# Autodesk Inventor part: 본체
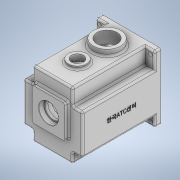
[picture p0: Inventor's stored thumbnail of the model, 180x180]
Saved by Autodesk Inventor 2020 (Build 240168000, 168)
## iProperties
Created: 2022-01
Part Number: 본체
Material: 일반
Document SubType Name: Modeling
Designer: user
Density: 1 g/cm^3
Appearance: 기본값
Author: user
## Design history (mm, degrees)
sketch "스케치1"
  geometry: L1 (-49, -55)-(49, -55); L2 (49, -55)-(49, 55); L3 (49, 55)-(-49, 55); L4 (-49, 55)-(-49, -55); L5 (-49, -55)-(49, 55); L6 (49, -55)-(-49, 55); 1 further point
  constraints: 12 end point, 2 midpoint, 2 parallel, 1 horizontal, 1 perpendicular
  dimensions: "d0" = 98 distance of L2.end L3.end; "d1" = 110 distance of L1.end L2.end
extrude "돌출1" new body sketch "스케치1" distance "d2" = 130; taper "d3" = 0 deg
sketch "스케치2"
  geometry: L1 (82, -130)-(98, -130); L2 (98, -130)-(98, -10); L3 (98, -10)-(82, -10); L4 (82, -10)-(82, -130); L5 (82, -130)-(98, -10); L6 (98, -130)-(82, -10); L7 (0, -130)-(16, -130); L8 (16, -130)-(16, -10); L9 (16, -10)-(0, -10); L10 (0, -10)-(0, -130); L11 (0, -130)-(16, -10); L12 (16, -130)-(0, -10); L13 (98, 0)-(0, 0) reference; 5 further points
  constraints: 24 end point, 4 midpoint, 4 parallel, 2 coincident, 2 horizontal, 2 perpendicular, 1 point on line
  dimensions: "d4" = 16 distance of L8.end L9.end; "d5" = 16 distance of L2.end L3.end; "d6" = 10 distance between parallel lines of L3 L13
extrude "돌출2" cut sketch "스케치2" distance "d7" = 27; taper "d8" = 0 deg
sketch "스케치3"
  geometry: L1 (16, 10)-(16, 130) reference; L2 (82, 130)-(82, 10) reference; L3 (0, 10)-(16, 10); L4 (16, 10)-(16, 130); L5 (16, 130)-(0, 130); L6 (0, 130)-(0, 10); L7 (0, 10)-(16, 130); L8 (16, 10)-(0, 130); L9 (82, 10)-(98, 10); L10 (98, 10)-(98, 130); L11 (98, 130)-(82, 130); L12 (82, 130)-(82, 10); L13 (82, 10)-(98, 130); L14 (98, 10)-(82, 130); L15 (0, 0)-(98, 0) reference; 9 further points
  constraints: 24 end point, 4 midpoint, 4 parallel, 2 coincident, 2 horizontal, 2 perpendicular, 1 point on line
  dimensions: "d9" = 16 distance between parallel lines of L4 L6; "d10" = 16 distance between parallel lines of L10 L12; "d11" = 10 distance between parallel lines of L15 L3; "d12" = 10 distance between parallel lines of L15 L9
extrude "돌출3" cut sketch "스케치3" distance "d13" = 17; taper "d14" = 0 deg
sketch "스케치5"
  geometry: L1 (49, -55)-(-49, -55) reference; L2 (23, 30.143)-(23, 45); L3 (23, 45)-(-23, 45); L4 (-23, 45)-(-23, 30.143); A1 r 42 centre (0, -5) between (-23, 30.143) and (23, 30.143); 1 further point
  constraints: 6 end point, 2 point on circle, 1 centre point, 1 parallel, 1 vertical alignment
  dimensions: "d23" = 84 diameter of A1; "d24" = 50 distance from line of L1 A1.centre; "d25" = 46 distance between parallel lines of L2 L4; "d26" = 50 distance from line of L3 A1.centre
extrude "돌출6" cut sketch "스케치5" distance "d27" = 121; taper "d28" = 0 deg
sketch "스케치7"
  geometry: L1 (-23, 45)-(23, 45) reference; L2 (-23, 30.143)-(-23, 45) reference; L3 (23, 45)-(23, 30.143) reference; L4 (26, 31.729)-(26, 48); L5 (26, 48)-(-26, 48); L6 (-26, 48)-(-26, 31.729); A1 r 42 centre (0, -5) between (-23, 30.143) and (23, 30.143) reference; A2 r 45 centre (0, -5) between (-26, 31.729) and (26, 31.729); 1 further point
  constraints: 6 end point, 2 point on circle, 1 centre point, 3 other
  dimensions: "d29" = 3 distance between parallel lines of L3 L4
extrude "돌출7" cut sketch "스케치7" distance "d30" = 9; taper "d31" = 0 deg
sketch "스케치8"
  geometry: L1 (98, 0)-(0, 0) reference; L2 (82, -10)-(98, -10) reference; L3 (98, 0)-(98, -10) reference; L4 (98, 0)-(0, 0) reference; L5 (0, 0)-(0, -10) reference; L6 (0, -10)-(16, -10) reference; L7 (16, -10)-(16, -130) reference; L8 (82, -130)-(16, -130) reference; L9 (82, -130)-(82, -10) reference; C1 r 22.5 at (49, -40); C2 r 15 at (49, -89); 2 further points
  constraints: 2 centre point, 2 vertical alignment, 1 midpoint
  dimensions: "d32" = 40 distance of point (49, 0) C1.centre; "d33" = 49 distance of C2.centre C1.centre; "d34" = 30 diameter of C2; "d35" = 45 diameter of C1
  node "투영된 루프1"
extrude "돌출8" join sketch "스케치8" distance "d36" = 10; taper "d37" = 0 deg
extrude "돌출9" join sketch "스케치8" distance "d38" = 5; taper "d39" = 0 deg
sketch "스케치9"
  geometry: C1 r 15 at (0, 0) reference; 2 further points
  constraints: 1 coincident
hole "구멍1" sketch "스케치9" at (0, 0) diameter "d40" = 20; stored, may be unused: countersink angle "d44" = 90 deg, drill point angle "d46" = 0 deg; dims "d41" = 10, "d42" = 4, "d43" = 2, "d45" = 55
sketch "스케치10"
  geometry: C1 r 10 at (23, -32) reference; C2 r 15 at (23, -32); 1 further point
  constraints: 1 centre point, 1 coincident
  dimensions: "d47" = 30 diameter of C2
extrude "돌출10" cut sketch "스케치10" distance "d48" = 5; taper "d49" = 0 deg
sketch "스케치11"
  geometry: C1 r 22.5 at (0, 0) reference; 2 further points
  constraints: 1 coincident
hole "구멍2" sketch "스케치11" at (0, 0) diameter "d50" = 33.376; stored, may be unused: countersink angle "d54" = 90 deg, drill point angle "d56" = 0 deg; dims "d51" = 52, "d52" = 4, "d53" = 2, "d55" = 55
sketch "스케치12"
  geometry: L1 (33, -55)-(-33, -55) reference; C1 r 15 at (0, -25); C2 r 21 at (0, 6); 3 further points
  constraints: 2 centre point
  dimensions: "d57" = 30 distance from line of L1 C1.centre; "d58" = 31 distance of C2.centre C1.centre; "d59" = 30 diameter of C1; "d60" = 42 diameter of C2
extrude "돌출11" join sketch "스케치12" distance "d61" = 7; taper "d62" = 0 deg
sketch "스케치13"
  geometry: C1 r 17.5 at (0, 6); A1 r 15 centre (0, -25) between (-8.978, -12.984) and (8.978, -12.984) reference; A2 r 21 centre (0, 6) between (8.978, -12.984) and (-8.978, -12.984) reference; 1 further point
  constraints: 1 centre point, 1 coincident
  dimensions: "d63" = 35 diameter of C1
extrude "돌출12" cut sketch "스케치13" distance "d64" = 10; taper "d65" = 0 deg
sketch "스케치17"
  geometry: L1 (-27, -21)-(27, -21); L2 (27, -21)-(27, 33); L3 (27, 33)-(-27, 33); L4 (-27, 33)-(-27, -21); L5 (-27, -21)-(27, 33); L6 (27, -21)-(-27, 33); C1 r 17.5 at (0, 6) reference; 2 further points
  constraints: 12 end point, 2 midpoint, 2 parallel, 1 horizontal, 1 perpendicular
  dimensions: "d66" = 54 distance of L2.end L3.end; "d67" = 54 distance of L1.end L2.end; "d68" = 27 distance from line of C1.centre L3
extrude "돌출13" join sketch "스케치17" distance "d69" = 7; taper "d70" = 0 deg
sketch "스케치19"
  geometry: C1 r 17.5 at (0, 6) reference; 1 further point
hole "구멍3" sketch "스케치19" at (0, 6) diameter "d71" = 28; stored, may be unused: countersink angle "d75" = 90 deg, drill point angle "d77" = 0 deg; dims "d72" = 52, "d73" = 32, "d74" = 8.3, "d76" = 10
sketch "스케치20"
  geometry: C1 r 17.5 at (0, 6) reference; A1 r 15 centre (0, -25) between (-8.978, -12.984) and (8.978, -12.984) reference; A2 r 21 centre (0, 6) between (8.978, -12.984) and (-8.978, -12.984) reference; 1 further point
hole "구멍4" sketch "스케치20" at (0, -25) diameter "d78" = 19; stored, may be unused: countersink angle "d82" = 90 deg, drill point angle "d84" = 0 deg; dims "d79" = 52, "d80" = 22, "d81" = 7, "d83" = 10
sketch "스케치22"
  geometry: L1 (-23, 30.143)-(-23, 45) reference; L2 (23, 45)-(23, 30.143) reference; L3 (-23, 45)-(23, 45) reference; L4 (-35.778, -1.006)-(-41.81, -1.006); L5 (35.778, -1.006)-(41.81, -1.006); L6 (-35.778, -8.994)-(-41.776, -9.328); L7 (35.778, -8.994)-(41.776, -9.328); C1 r 9.5 at (0, -25) reference; C2 r 14 at (0, 6) reference; A1 r 21 centre (0, 6) between (8.978, -12.984) and (-8.978, -12.984) reference; A2 r 15 centre (0, -25) between (-8.978, -12.984) and (8.978, -12.984) reference; A3 r 42 centre (0, -5) between (-23, 30.143) and (23, 30.143) reference; A4 r 36 centre (0, -5) between (-36, -5) and (36, -5); A5 r 4 centre (-36, -5) between (-35.778, -1.006) and (-35.778, -8.994); A6 r 4 centre (36, -5) between (35.778, -1.006) and (35.778, -8.994); A7 r 42 centre (0, -5) between (-23, 30.143) and (23, 30.143) reference; 4 further points
  constraints: 14 point on circle, 8 end point, 3 centre point, 2 horizontal alignment, 2 tangent, 1 coincident, 1 horizontal, 1 point on line
  dimensions: "d86" = 72 diameter of A4; "d87" = 8 diameter of A5; "d88" = 8 diameter of A6
extrude "돌출14" join sketch "스케치22" stored distance "d89" = 105; taper "d90" = 0 deg
sketch "스케치23"
  geometry: A1 r 4 centre (-36, -5) between (-35.778, -8.994) and (-36.222, -1.006) reference; 2 further points
  constraints: 1 coincident
hole "구멍5" sketch "스케치23" at (-36, -5) diameter "d91" = 3.242; stored, may be unused: countersink angle "d95" = 90 deg, drill point angle "d97" = 118 deg; dims "d92" = 7, "d93" = 22, "d94" = 7, "d96" = 9
sketch "스케치24"
  geometry: A1 r 4 centre (36, -5) between (35.778, -1.006) and (35.778, -8.994) reference; 2 further points
  constraints: 1 coincident
hole "구멍6" sketch "스케치24" at (36, -5) diameter "d98" = 3.242; stored, may be unused: countersink angle "d102" = 90 deg, drill point angle "d104" = 118 deg; dims "d99" = 7, "d100" = 22, "d101" = 7, "d103" = 9
sketch "스케치25"
  geometry: L1 (-49, -55)-(-49, 55) reference; L2 (-49, 55)-(49, 55) reference; 2 further points
  dimensions: "d105" = 7 distance from line of L1 point (-42, 48); "d106" = 7 distance from line of L2 point (-42, 48)
hole "구멍7" sketch "스케치25" at (-42, 48) diameter "d107" = 7; stored, may be unused: countersink angle "d111" = 90 deg, drill point angle "d113" = 0 deg; dims "d108" = 7, "d109" = 22, "d110" = 7, "d112" = 9
sketch "스케치26"
  geometry: 1 further point
sketch "스케치27"
  geometry: 1 further point
fillet "모깎기1" dims "d114" = 0.3
chamfer "모따기1" distance "d115" = 1; stored, may be unused: second distance "d116" = 2, angle "d117" = 45 deg
chamfer "모따기2" distance "d118" = 0.8; stored, may be unused: second distance "d119" = 2, angle "d120" = 30 deg
fillet "모깎기3" dims "d122" = 3
fillet "모깎기4" dims "d123" = 3
fillet "모깎기5" dims "d127" = 3
fillet "모깎기6" dims "d128" = 3
fillet "모깎기7" dims "d129" = 3
fillet "모깎기8" dims "d130" = 3
fillet "모깎기9" dims "d131" = 3
fillet "모깎기10" dims "d132" = 3
fillet "모깎기11" dims "d133" = 3
fillet "모깎기12" dims "d134" = 3
sketch "스케치28"
  geometry: L1 (-10, 80)-(-127, 80) reference; L2 (-130, 104)-(-130, 83) reference; 2 further points
  constraints: 1 other
  dimensions: "d135" = 33 distance from line of point (-65, 47) L1; "d136" = 65 distance from line of L2 point (-65, 47)
feature "엠보싱1" sketch "스케치28" dims "d137" = 0.5, "d138" = 0
fillet "모깎기13" dims "d139" = 6
fillet "모깎기14" dims "d140" = 6
fillet "모깎기15" dims "d141" = 3
chamfer "모따기4" distance "d142" = 1; stored, may be unused: second distance "d143" = 2, angle "d144" = 30 deg
chamfer "모따기5" distance "d145" = 1; stored, may be unused: second distance "d146" = 2, angle "d147" = 30 deg
chamfer "모따기6" distance "d148" = 1; stored, may be unused: second distance "d149" = 2, angle "d150" = 30 deg
node "솔리드1"
mirror "미러1"
mirror "미러2"
node "투영된 루프2"
node "투영된 루프4"
node "투영된 루프5"
node "투영된 루프6"
node "투영된 루프8"
node "투영된 루프9"
feature "A9D066F2-1C7D-4E18-AEED-F7BC21143FA4" dims "d40" = 20, "d41" = 10, "d42" = 4, "d43" = 2, "d44" = 90 deg, "d45" = 55, "d46" = 0
